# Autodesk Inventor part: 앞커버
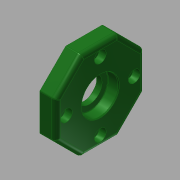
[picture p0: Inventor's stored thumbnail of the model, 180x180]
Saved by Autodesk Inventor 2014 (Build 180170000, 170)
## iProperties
Created: 2015-11
Part Number: 앞커버
Material: 알루미늄 6061
Document SubType Name: Modeling
Designer: mduedu
Density: 1 g/cm^3
Appearance: 매끄러움 - 짙은 산림 녹색
Author: mduedu
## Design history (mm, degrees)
sketch "스케치5" dims "d66" = 60
  geometry: L1 (12.426, 30)-(30, 12.426); L2 (30, 12.426)-(30, -12.426); L3 (30, -12.426)-(12.426, -30); L4 (12.426, -30)-(-12.426, -30); L5 (-12.426, -30)-(-30, -12.426); L6 (-30, -12.426)-(-30, 12.426); L7 (-30, 12.426)-(-12.426, 30); L8 (-12.426, 30)-(12.426, 30); 4 further points
  constraints: 16 end point, 2 coincident, 2 vertical alignment, 1 midpoint, 19 other
extrude "돌출2" new body sketch "스케치5" distance "d67" = 11; taper "d68" = 0 deg
sketch "스케치6"
  geometry: C1 r 16 at (0, 0); 1 further point
  constraints: 1 centre point, 1 coincident
  dimensions: "d69" = 32 diameter of C1
extrude "돌출3" join sketch "스케치6" distance "d70" = 3; taper "d71" = 0 deg
hole "구멍7" diameter "d98" = 25; stored, may be unused: countersink angle "d102" = 90 deg, drill point angle "d104" = 0 deg; dims "d96" = 10, "d97" = 10, "d99" = 6, "d100" = 4, "d101" = 2, "d103" = 3
hole "구멍8" diameter "d107" = 25; stored, may be unused: countersink angle "d111" = 90 deg, drill point angle "d113" = 0 deg; dims "d108" = 6, "d109" = 4, "d110" = 2, "d112" = 7.3, "d143" = 10, "d144" = 10
hole "구멍9" diameter "d116" = 17; stored, may be unused: countersink angle "d120" = 90 deg, drill point angle "d122" = 0 deg; dims "d114" = 10, "d115" = 10, "d117" = 6, "d118" = 4, "d119" = 2, "d121" = 7.7
chamfer "모따기2" distance "d123" = 0.7; stored, may be unused: second distance "d124" = 2, angle "d125" = 30 deg
fillet "모깎기11" dims "d126" = 0.3
fillet "모깎기12" dims "d127" = 1
fillet "모깎기13" dims "d128" = 3
fillet "모깎기14" dims "d129" = 3
fillet "모깎기15" dims "d130" = 0.3
sketch "스케치8" dims "d131" = 46
  geometry: 3 further points
  constraints: 2 vertical alignment, 1 coincident, 2 other
hole "구멍10" sketch "스케치8" at (0, 23) diameter "d132" = 4.5; stored, may be unused: countersink angle "d136" = 90 deg, drill point angle "d138" = 0 deg; dims "d133" = 6, "d134" = 8, "d135" = 4.6, "d137" = 7.7
node "솔리드2"
pattern_circular "원형 패턴4" dims angle "d140" = 360 deg
